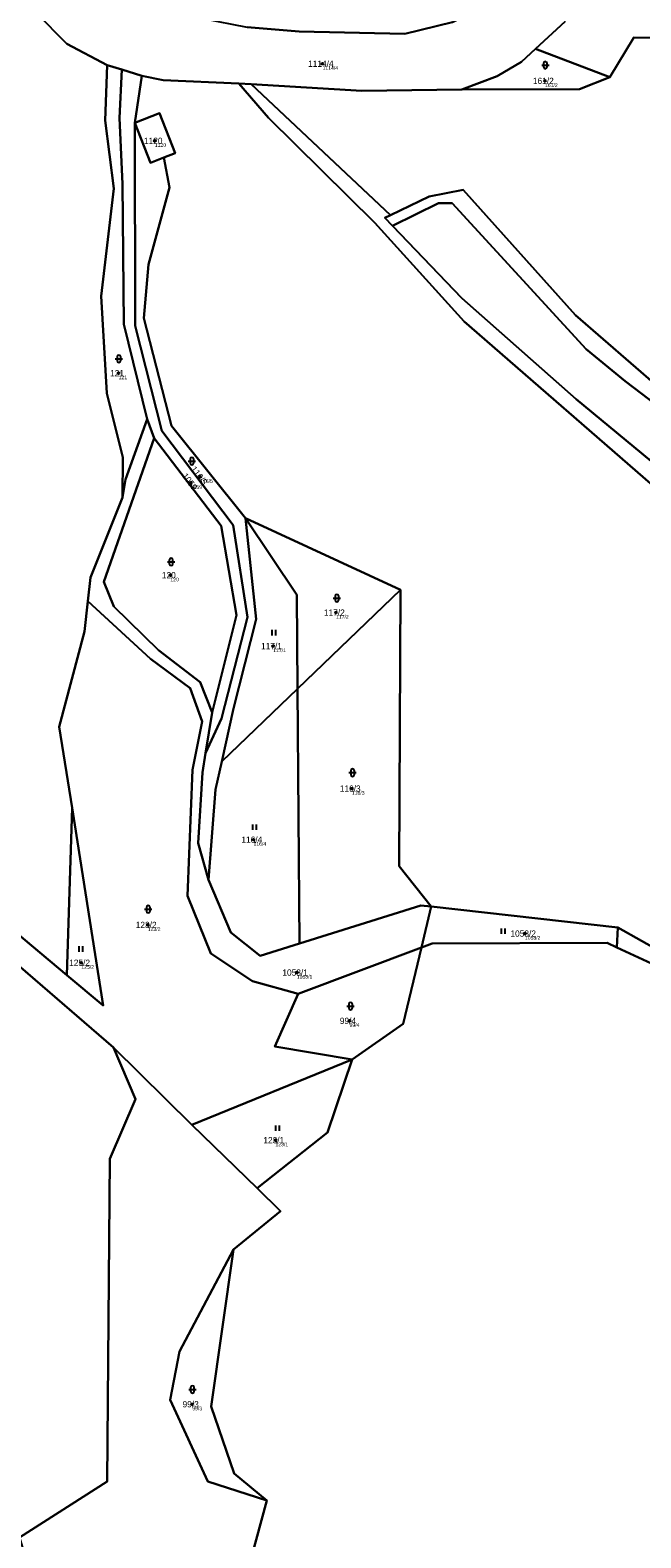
# Model space of a CAD drawing. Extents: x -554500 to -548272, y -1079733 to -1073730.
# Drawn here: x -552811.3 to -552644.9, y -1077438.3 to -1077027.7 of the extents above; entities that cross this region are included whole.
import ezdxf

# ---------------------------------------------------------------- set-up
doc = ezdxf.new("R2010")
doc.units = 0
for name, color, linetype in [('Definiční body', 7, 'Continuous'), ('Hranice parcel', 7, 'Continuous'), ('Parcelní čísla', 7, 'Continuous'), ('Polygon parcely', 7, 'Continuous'), ('Značky kultur', 7, 'Continuous')]:
    doc.layers.add(name, color=color, linetype=linetype)

msp = doc.modelspace()

# ---------------------------------------------------------------- linework, layer by layer
at = {"layer": 'Definiční body'}
for centre in [(-552731.61, -1077036.85994), (-552671.02, -1077041.52994), (-552777.3, -1077057.84994), (-552787.17, -1077121.10994), (-552767.53, -1077150.99994), (-552764.95, -1077149.35994), (-552773.07, -1077176.13994), (-552727.95, -1077186.31994), (-552745.07, -1077195.43994), (-552723.63, -1077234.24994), (-552750.43, -1077248.15994), (-552779.22, -1077271.36994), (-552676.49, -1077273.72994), (-552797.34, -1077281.66994), (-552738.62, -1077284.33994), (-552724.27, -1077297.48994), (-552744.45, -1077329.98994), (-552767.11, -1077401.89994)]:
    msp.add_circle(centre, 0.25, dxfattribs=at)
at = {"layer": 'Hranice parcel'}
for p, q in [((-552665.53, -1077025.33), (-552673.59, -1077032.78)), ((-552673.59, -1077032.78), (-552653.4, -1077040.52)), ((-552786.28, -1077038.47), (-552790.28, -1077037.21)), ((-552780.86, -1077040.17), (-552786.28, -1077038.47)), ((-552782.79, -1077052.97), (-552780.86, -1077040.17)), ((-552751.02, -1077042.45), (-552754.44, -1077042.24)), ((-552713.14, -1077078.13), (-552751.02, -1077042.45)), ((-552777.52, -1077138.83), (-552779.42, -1077133.62)), ((-552710.35, -1077180.11), (-552752.62, -1077160.65)), ((-552710.35, -1077180.11), (-552738.46, -1077207.05)), ((-552738.46, -1077207.05), (-552759.1, -1077226.83)), ((-552738.46, -1077207.05), (-552737.9, -1077276.43)), ((-552763.49, -1077224.58), (-552761.73, -1077213.52)), ((-552801.28, -1077285.01), (-552799.86, -1077239.46)), ((-552801.28, -1077285.01), (-552841.18, -1077251.64)), ((-552788.55, -1077304.75), (-552844.64, -1077256.35)), ((-552704.66, -1077277.49), (-552701.99, -1077266.38)), ((-552651.16, -1077272.05), (-552701.99, -1077266.38)), ((-552651.47, -1077277.5), (-552651.16, -1077272.05)), ((-552638.3, -1077279.34), (-552651.16, -1077272.05)), ((-552704.66, -1077277.49), (-552738.29, -1077290.17)), ((-552767.19, -1077325.78), (-552788.55, -1077304.75)), ((-552723.58, -1077307.99), (-552767.19, -1077325.78)), ((-552749.44, -1077343.09), (-552767.19, -1077325.78))]:
    msp.add_line(p, q, dxfattribs=at)
for points in [[(-552805.21, -1076999.91), (-552796.09, -1077011.92), (-552787.96, -1077017.54), (-552784.15, -1077019.17), (-552776.33, -1077022.15), (-552752.12, -1077026.89), (-552738.02, -1077028.06), (-552709.18, -1077028.68), (-552696.24, -1077025.5), (-552682.97, -1077018.58), (-552675.22, -1077011.97), (-552652.82, -1076990.23)], [(-552790.28, -1077037.21), (-552801.32, -1077031.45), (-552809.74, -1077022.87), (-552827.85, -1076998.45)], [(-552673.59, -1077032.78), (-552677.43, -1077036.32), (-552684.05, -1077040.25), (-552693.64, -1077043.85)], [(-552653.4, -1077040.52), (-552646.86, -1077029.76), (-552624.45, -1077030.16), (-552597.47, -1077040.98), (-552582.84, -1077051.52), (-552573.74, -1077062.51), (-552541.1, -1077125.95), (-552535.28, -1077141.98), (-552500.58, -1077183.57), (-552484.84, -1077224.94), (-552483.73, -1077240.24), (-552477.24, -1077252.97), (-552476.8, -1077265.1)], [(-552790.28, -1077037.21), (-552790.84, -1077052.29), (-552788.5, -1077070.86), (-552791.92, -1077100.14), (-552790.34, -1077126.56), (-552786, -1077144.13), (-552786.09, -1077154.96)], [(-552779.42, -1077133.62), (-552785.78, -1077107.8), (-552786.1, -1077069.57), (-552786.9, -1077051.73), (-552786.28, -1077038.47)], [(-552780.86, -1077040.17), (-552775.06, -1077041.37), (-552754.44, -1077042.24)], [(-552653.4, -1077040.52), (-552661.58, -1077043.75), (-552693.64, -1077043.85)], [(-552754.44, -1077042.24), (-552746.3, -1077051.58), (-552717.37, -1077080.17), (-552693.04, -1077107.1), (-552638.13, -1077154.8), (-552603.73, -1077178.22), (-552577.89, -1077200.85), (-552553.67, -1077225.19), (-552518.05, -1077258.47), (-552487.02, -1077289.2)], [(-552693.64, -1077043.85), (-552720.94, -1077044.25), (-552751.02, -1077042.45)], [(-552774.83, -1077062.44), (-552771.73, -1077061.22), (-552776.05, -1077050.3), (-552782.79, -1077052.97)], [(-552774.83, -1077062.44), (-552778.47, -1077063.89), (-552782.79, -1077052.97)], [(-552782.79, -1077052.97), (-552782.69, -1077108.27), (-552775.41, -1077136.87), (-552755.95, -1077162.5), (-552752.08, -1077187.6), (-552759.18, -1077215.17), (-552763.49, -1077224.58)], [(-552752.62, -1077160.65), (-552772.79, -1077135.47), (-552780.31, -1077106.19), (-552779.01, -1077091.53), (-552773.27, -1077070.61), (-552774.83, -1077062.44)], [(-552476.8, -1077265.1), (-552489.86, -1077252.25), (-552539.07, -1077208.1), (-552586.76, -1077160.47), (-552599.88, -1077151.51), (-552619.68, -1077140.24), (-552640.06, -1077124.94), (-552662.67, -1077105.32), (-552693.33, -1077071.21), (-552702.61, -1077073.03), (-552713.14, -1077078.13)], [(-552478.63, -1077269.41), (-552542.48, -1077211.84), (-552572.59, -1077182.17), (-552592.21, -1077162.02), (-552627.59, -1077139.76), (-552649.14, -1077123.28), (-552659.79, -1077114.63), (-552696.32, -1077074.8), (-552700.01, -1077074.81), (-552712.57, -1077081.01)], [(-552712.57, -1077081.01), (-552714.62, -1077078.84), (-552713.14, -1077078.13)], [(-552712.57, -1077081.01), (-552693.7, -1077100.73), (-552662.54, -1077128.22), (-552640.05, -1077146.78), (-552599.65, -1077176.96), (-552576.15, -1077197.49), (-552551, -1077222.01), (-552528.61, -1077242.66), (-552484.99, -1077284.42)], [(-552786.09, -1077154.96), (-552785.27, -1077150.08), (-552779.42, -1077133.62)], [(-552777.52, -1077138.83), (-552791.17, -1077177.91), (-552788.44, -1077184.63), (-552776.28, -1077196.53), (-552764.96, -1077205.25), (-552761.73, -1077213.52)], [(-552761.73, -1077213.52), (-552755.08, -1077186.99), (-552759.26, -1077162.72), (-552777.52, -1077138.83)], [(-552795.55, -1077183.21), (-552794.82, -1077176.81), (-552786.09, -1077154.96)], [(-552759.1, -1077226.83), (-552755.89, -1077212.41), (-552749.69, -1077188.09), (-552752.62, -1077160.65)], [(-552738.46, -1077207.05), (-552738.66, -1077181.5), (-552752.62, -1077160.65)], [(-552701.99, -1077266.38), (-552710.72, -1077255.41), (-552710.35, -1077180.11)], [(-552795.55, -1077183.21), (-552796.5, -1077191.49), (-552803.34, -1077217.43), (-552799.86, -1077239.46)], [(-552738.29, -1077290.17), (-552750.74, -1077286.66), (-552762.01, -1077279.12), (-552768.44, -1077263.43), (-552767.06, -1077229.18), (-552764.41, -1077216.02), (-552767.68, -1077206.93), (-552778.46, -1077198.92), (-552795.55, -1077183.21)], [(-552763.49, -1077224.58), (-552764.34, -1077229.9), (-552765.51, -1077249.1), (-552762.67, -1077259.09)], [(-552759.1, -1077226.83), (-552760.81, -1077234.48), (-552762.67, -1077259.09)], [(-552799.86, -1077239.46), (-552791.36, -1077293.31), (-552801.28, -1077285.01)], [(-552762.67, -1077259.09), (-552756.57, -1077273.48), (-552748.64, -1077279.8), (-552737.9, -1077276.43)], [(-552737.9, -1077276.43), (-552704.88, -1077266.06), (-552701.99, -1077266.38)], [(-552704.66, -1077277.49), (-552709.68, -1077298.34), (-552723.58, -1077307.99)], [(-552651.47, -1077277.5), (-552654.1, -1077276.28), (-552701.8, -1077276.41), (-552704.66, -1077277.49)], [(-552576.25, -1077376.33), (-552603.81, -1077361.54), (-552633.04, -1077349.32), (-552636.22, -1077339.19), (-552628.43, -1077303.5), (-552639.68, -1077282.97), (-552651.47, -1077277.5)], [(-552738.29, -1077290.17), (-552744.61, -1077304.51), (-552723.58, -1077307.99)], [(-552814.18, -1077438.2), (-552790.32, -1077422.91), (-552789.58, -1077335.11), (-552782.56, -1077318.81), (-552788.55, -1077304.75)], [(-552723.58, -1077307.99), (-552730.31, -1077327.86), (-552749.44, -1077343.09)], [(-552755.92, -1077359.75), (-552743.05, -1077349.32), (-552749.44, -1077343.09)], [(-552746.76, -1077428.1), (-552762.91, -1077422.95), (-552773.13, -1077400.7), (-552770.63, -1077387.54), (-552755.92, -1077359.75)], [(-552755.92, -1077359.75), (-552761.99, -1077402.52), (-552755.65, -1077420.71), (-552746.76, -1077428.1)], [(-552718.43, -1077507.71), (-552730.56, -1077479.12), (-552740.95, -1077471.44), (-552752.64, -1077449.51), (-552746.76, -1077428.1)]]:
    msp.add_lwpolyline(points, dxfattribs=at)
at = {"layer": 'Polygon parcely'}
for points in [[(-552776.33, -1077022.15), (-552752.12, -1077026.89), (-552738.02, -1077028.06), (-552709.18, -1077028.68), (-552696.24, -1077025.5), (-552682.97, -1077018.58), (-552675.22, -1077011.97), (-552652.82, -1076990.23), (-552665.24, -1076993.3), (-552745.16, -1077003.8), (-552805.21, -1076999.91), (-552796.09, -1077011.92), (-552787.96, -1077017.54), (-552784.15, -1077019.17)], [(-552684.05, -1077040.25), (-552693.64, -1077043.85), (-552661.58, -1077043.75), (-552653.4, -1077040.52), (-552673.59, -1077032.78), (-552677.43, -1077036.32)], [(-552786, -1077144.13), (-552786.09, -1077154.96), (-552785.27, -1077150.08), (-552779.42, -1077133.62), (-552785.78, -1077107.8), (-552786.1, -1077069.57), (-552786.9, -1077051.73), (-552786.28, -1077038.47), (-552790.28, -1077037.21), (-552790.84, -1077052.29), (-552788.5, -1077070.86), (-552791.92, -1077100.14), (-552790.34, -1077126.56)], [(-552780.86, -1077040.17), (-552786.28, -1077038.47), (-552786.9, -1077051.73), (-552786.1, -1077069.57), (-552785.78, -1077107.8), (-552779.42, -1077133.62), (-552777.52, -1077138.83), (-552759.26, -1077162.72), (-552755.08, -1077186.99), (-552761.73, -1077213.52), (-552763.49, -1077224.58), (-552759.18, -1077215.17), (-552752.08, -1077187.6), (-552755.95, -1077162.5), (-552775.41, -1077136.87), (-552782.69, -1077108.27), (-552782.79, -1077052.97)], [(-552751.02, -1077042.45), (-552754.44, -1077042.24), (-552746.3, -1077051.58), (-552717.37, -1077080.17), (-552693.04, -1077107.1), (-552638.13, -1077154.8), (-552603.73, -1077178.22), (-552577.89, -1077200.85), (-552553.67, -1077225.19), (-552518.05, -1077258.47), (-552487.02, -1077289.2), (-552484.99, -1077284.42), (-552528.61, -1077242.66), (-552551, -1077222.01), (-552576.15, -1077197.49), (-552599.65, -1077176.96), (-552640.05, -1077146.78), (-552662.54, -1077128.22), (-552693.7, -1077100.73), (-552712.57, -1077081.01), (-552714.62, -1077078.84), (-552713.14, -1077078.13)], [(-552771.73, -1077061.22), (-552776.05, -1077050.3), (-552782.79, -1077052.97), (-552778.47, -1077063.89), (-552774.83, -1077062.44)], [(-552775.41, -1077136.87), (-552755.95, -1077162.5), (-552752.08, -1077187.6), (-552759.18, -1077215.17), (-552763.49, -1077224.58), (-552764.34, -1077229.9), (-552765.51, -1077249.1), (-552762.67, -1077259.09), (-552760.81, -1077234.48), (-552759.1, -1077226.83), (-552755.89, -1077212.41), (-552749.69, -1077188.09), (-552752.62, -1077160.65), (-552772.79, -1077135.47), (-552780.31, -1077106.19), (-552779.01, -1077091.53), (-552773.27, -1077070.61), (-552774.83, -1077062.44), (-552778.47, -1077063.89), (-552782.79, -1077052.97), (-552782.69, -1077108.27)], [(-552599.88, -1077151.51), (-552619.68, -1077140.24), (-552640.06, -1077124.94), (-552662.67, -1077105.32), (-552693.33, -1077071.21), (-552702.61, -1077073.03), (-552713.14, -1077078.13), (-552714.62, -1077078.84), (-552712.57, -1077081.01), (-552700.01, -1077074.81), (-552696.32, -1077074.8), (-552659.79, -1077114.63), (-552649.14, -1077123.28), (-552627.59, -1077139.76), (-552592.21, -1077162.02), (-552572.59, -1077182.17), (-552542.48, -1077211.84), (-552478.63, -1077269.41), (-552476.8, -1077265.1), (-552489.86, -1077252.25), (-552539.07, -1077208.1), (-552586.76, -1077160.47)], [(-552528.61, -1077242.66), (-552484.99, -1077284.42), (-552478.63, -1077269.41), (-552542.48, -1077211.84), (-552572.59, -1077182.17), (-552592.21, -1077162.02), (-552627.59, -1077139.76), (-552649.14, -1077123.28), (-552659.79, -1077114.63), (-552696.32, -1077074.8), (-552700.01, -1077074.81), (-552712.57, -1077081.01), (-552693.7, -1077100.73), (-552662.54, -1077128.22), (-552640.05, -1077146.78), (-552599.65, -1077176.96), (-552576.15, -1077197.49), (-552551, -1077222.01)], [(-552777.52, -1077138.83), (-552779.42, -1077133.62), (-552785.27, -1077150.08), (-552786.09, -1077154.96), (-552794.82, -1077176.81), (-552795.55, -1077183.21), (-552778.46, -1077198.92), (-552767.68, -1077206.93), (-552764.41, -1077216.02), (-552767.06, -1077229.18), (-552768.44, -1077263.43), (-552762.01, -1077279.12), (-552750.74, -1077286.66), (-552738.29, -1077290.17), (-552704.66, -1077277.49), (-552701.99, -1077266.38), (-552704.88, -1077266.06), (-552737.9, -1077276.43), (-552748.64, -1077279.8), (-552756.57, -1077273.48), (-552762.67, -1077259.09), (-552765.51, -1077249.1), (-552764.34, -1077229.9), (-552763.49, -1077224.58), (-552761.73, -1077213.52), (-552764.96, -1077205.25), (-552776.28, -1077196.53), (-552788.44, -1077184.63), (-552791.17, -1077177.91)], [(-552759.26, -1077162.72), (-552777.52, -1077138.83), (-552791.17, -1077177.91), (-552788.44, -1077184.63), (-552776.28, -1077196.53), (-552764.96, -1077205.25), (-552761.73, -1077213.52), (-552755.08, -1077186.99)], [(-552738.66, -1077181.5), (-552752.62, -1077160.65), (-552749.69, -1077188.09), (-552755.89, -1077212.41), (-552759.1, -1077226.83), (-552738.46, -1077207.05)], [(-552752.62, -1077160.65), (-552738.66, -1077181.5), (-552738.46, -1077207.05), (-552710.35, -1077180.11)], [(-552710.72, -1077255.41), (-552710.35, -1077180.11), (-552738.46, -1077207.05), (-552737.9, -1077276.43), (-552704.88, -1077266.06), (-552701.99, -1077266.38)], [(-552796.5, -1077191.49), (-552803.34, -1077217.43), (-552799.86, -1077239.46), (-552791.36, -1077293.31), (-552801.28, -1077285.01), (-552841.18, -1077251.64), (-552844.64, -1077256.35), (-552788.55, -1077304.75), (-552767.19, -1077325.78), (-552723.58, -1077307.99), (-552744.61, -1077304.51), (-552738.29, -1077290.17), (-552750.74, -1077286.66), (-552762.01, -1077279.12), (-552768.44, -1077263.43), (-552767.06, -1077229.18), (-552764.41, -1077216.02), (-552767.68, -1077206.93), (-552778.46, -1077198.92), (-552795.55, -1077183.21)], [(-552748.64, -1077279.8), (-552737.9, -1077276.43), (-552738.46, -1077207.05), (-552759.1, -1077226.83), (-552760.81, -1077234.48), (-552762.67, -1077259.09), (-552756.57, -1077273.48)], [(-552801.28, -1077285.01), (-552791.36, -1077293.31), (-552799.86, -1077239.46)], [(-552651.16, -1077272.05), (-552701.99, -1077266.38), (-552704.66, -1077277.49), (-552701.8, -1077276.41), (-552654.1, -1077276.28), (-552651.47, -1077277.5)], [(-552704.66, -1077277.49), (-552738.29, -1077290.17), (-552744.61, -1077304.51), (-552723.58, -1077307.99), (-552709.68, -1077298.34)], [(-552814.18, -1077438.2), (-552812.92, -1077442.41), (-552802.21, -1077490.63), (-552792.48, -1077506.22), (-552767.39, -1077531.22), (-552747.77, -1077536.2), (-552740.65, -1077529.91), (-552718.43, -1077507.71), (-552730.56, -1077479.12), (-552740.95, -1077471.44), (-552752.64, -1077449.51), (-552746.76, -1077428.1), (-552762.91, -1077422.95), (-552773.13, -1077400.7), (-552770.63, -1077387.54), (-552755.92, -1077359.75), (-552743.05, -1077349.32), (-552749.44, -1077343.09), (-552767.19, -1077325.78), (-552788.55, -1077304.75), (-552782.56, -1077318.81), (-552789.58, -1077335.11), (-552790.32, -1077422.91)], [(-552767.19, -1077325.78), (-552749.44, -1077343.09), (-552730.31, -1077327.86), (-552723.58, -1077307.99)], [(-552755.92, -1077359.75), (-552770.63, -1077387.54), (-552773.13, -1077400.7), (-552762.91, -1077422.95), (-552746.76, -1077428.1), (-552755.65, -1077420.71), (-552761.99, -1077402.52)]]:
    msp.add_lwpolyline(points, close=True, dxfattribs=at)
for points in [[(-553044.61, -1077004.06), (-552978.82, -1077104.33), (-552881.84, -1077206.3), (-552841.18, -1077251.64), (-552801.28, -1077285.01), (-552799.86, -1077239.46), (-552803.34, -1077217.43), (-552796.5, -1077191.49), (-552795.55, -1077183.21), (-552794.82, -1077176.81), (-552786.09, -1077154.96), (-552786, -1077144.13), (-552790.34, -1077126.56), (-552791.92, -1077100.14), (-552788.5, -1077070.86), (-552790.84, -1077052.29), (-552790.28, -1077037.21), (-552801.32, -1077031.45), (-552809.74, -1077022.87)], [(-553088.19, -1077027.01), (-552985.99, -1077147.62), (-552933.72, -1077198.89), (-552901.01, -1077235.78), (-552861.41, -1077268.32), (-552864.7, -1077296.68), (-552876.19, -1077304.96), (-552869.04, -1077332.78), (-552857.32, -1077356.74), (-552823.97, -1077405.02), (-552814.18, -1077438.2), (-552790.32, -1077422.91), (-552789.58, -1077335.11), (-552782.56, -1077318.81), (-552788.55, -1077304.75), (-552844.64, -1077256.35), (-552874.93, -1077221.44), (-552913.63, -1077181.25), (-552981.06, -1077107.64), (-553022.78, -1077046.48), (-553047.15, -1077007.87)], [(-552809.74, -1077022.87), (-552801.32, -1077031.45), (-552790.28, -1077037.21), (-552786.28, -1077038.47), (-552780.86, -1077040.17), (-552775.06, -1077041.37), (-552754.44, -1077042.24), (-552751.02, -1077042.45), (-552720.94, -1077044.25), (-552693.64, -1077043.85), (-552684.05, -1077040.25), (-552677.43, -1077036.32), (-552673.59, -1077032.78), (-552665.53, -1077025.33)], [(-552696.24, -1077025.5), (-552709.18, -1077028.68), (-552738.02, -1077028.06), (-552752.12, -1077026.89)], [(-552665.53, -1077025.33), (-552673.59, -1077032.78), (-552653.4, -1077040.52), (-552646.86, -1077029.76), (-552624.45, -1077030.16)], [(-552624.45, -1077030.16), (-552646.86, -1077029.76), (-552653.4, -1077040.52), (-552661.58, -1077043.75), (-552693.64, -1077043.85), (-552720.94, -1077044.25), (-552751.02, -1077042.45), (-552713.14, -1077078.13), (-552702.61, -1077073.03), (-552693.33, -1077071.21), (-552662.67, -1077105.32), (-552640.06, -1077124.94)], [(-552638.13, -1077154.8), (-552693.04, -1077107.1), (-552717.37, -1077080.17), (-552746.3, -1077051.58), (-552754.44, -1077042.24), (-552775.06, -1077041.37), (-552780.86, -1077040.17), (-552782.79, -1077052.97), (-552776.05, -1077050.3), (-552771.73, -1077061.22), (-552774.83, -1077062.44), (-552773.27, -1077070.61), (-552779.01, -1077091.53), (-552780.31, -1077106.19), (-552772.79, -1077135.47), (-552752.62, -1077160.65), (-552710.35, -1077180.11), (-552710.72, -1077255.41), (-552701.99, -1077266.38), (-552651.16, -1077272.05), (-552638.3, -1077279.34)], [(-552473.23, -1077492.5), (-552525.21, -1077414.79), (-552561.07, -1077381.56), (-552603.6, -1077358.49), (-552630.95, -1077347.33), (-552633.72, -1077337.84), (-552625.91, -1077301.85), (-552638.3, -1077279.34), (-552651.16, -1077272.05), (-552651.47, -1077277.5), (-552639.68, -1077282.97), (-552628.43, -1077303.5), (-552636.22, -1077339.19), (-552633.04, -1077349.32), (-552603.81, -1077361.54), (-552576.25, -1077376.33), (-552563.13, -1077383.33), (-552528.11, -1077416.15), (-552476.28, -1077492.8)], [(-552492.14, -1077480), (-552531.25, -1077419.85), (-552576.25, -1077376.33), (-552603.81, -1077361.54), (-552633.04, -1077349.32), (-552636.22, -1077339.19), (-552628.43, -1077303.5), (-552639.68, -1077282.97), (-552651.47, -1077277.5), (-552654.1, -1077276.28), (-552701.8, -1077276.41), (-552704.66, -1077277.49), (-552709.68, -1077298.34), (-552723.58, -1077307.99), (-552730.31, -1077327.86), (-552749.44, -1077343.09), (-552743.05, -1077349.32), (-552755.92, -1077359.75), (-552761.99, -1077402.52), (-552755.65, -1077420.71), (-552746.76, -1077428.1), (-552752.64, -1077449.51)]]:
    msp.add_lwpolyline(points, dxfattribs=at)
at = {"layer": 'Značky kultur'}
for p, q in [((-552671.421, -1077036.751), (-552671.421, -1077037.752)), ((-552670.419, -1077037.752), (-552670.419, -1077036.751)), ((-552671.921, -1077037.251), (-552669.919, -1077037.251)), ((-552788.091, -1077117.181), (-552786.089, -1077117.181)), ((-552787.591, -1077116.681), (-552787.591, -1077117.682)), ((-552786.589, -1077117.682), (-552786.589, -1077116.681)), ((-552768.201, -1077145.071), (-552766.199, -1077145.071)), ((-552767.701, -1077144.571), (-552767.701, -1077145.572)), ((-552766.699, -1077145.572), (-552766.699, -1077144.571)), ((-552773.871, -1077172.511), (-552771.869, -1077172.511)), ((-552773.371, -1077172.011), (-552773.371, -1077173.012)), ((-552772.369, -1077173.012), (-552772.369, -1077172.011)), ((-552728.701, -1077182.351), (-552726.699, -1077182.351)), ((-552728.201, -1077181.851), (-552728.201, -1077182.852)), ((-552727.199, -1077182.852), (-552727.199, -1077181.851)), ((-552745.361, -1077192.55), (-552745.361, -1077191.05)), ((-552744.36, -1077192.55), (-552744.36, -1077191.05)), ((-552724.431, -1077229.911), (-552722.429, -1077229.911)), ((-552723.931, -1077229.411), (-552723.931, -1077230.412)), ((-552722.929, -1077230.412), (-552722.929, -1077229.411)), ((-552750.641, -1077245.51), (-552750.641, -1077244.01)), ((-552749.64, -1077245.51), (-552749.64, -1077244.01)), ((-552779.591, -1077266.591), (-552779.591, -1077267.592)), ((-552778.589, -1077267.592), (-552778.589, -1077266.591)), ((-552780.091, -1077267.091), (-552778.089, -1077267.091)), ((-552682.891, -1077273.84), (-552682.891, -1077272.34)), ((-552681.89, -1077273.84), (-552681.89, -1077272.34)), ((-552797.961, -1077278.67), (-552797.961, -1077277.17)), ((-552796.96, -1077278.67), (-552796.96, -1077277.17)), ((-552724.991, -1077293.481), (-552722.989, -1077293.481)), ((-552724.491, -1077292.981), (-552724.491, -1077293.982)), ((-552723.489, -1077293.982), (-552723.489, -1077292.981)), ((-552744.351, -1077327.45), (-552744.351, -1077325.95)), ((-552743.35, -1077327.45), (-552743.35, -1077325.95)), ((-552768.061, -1077397.841), (-552766.059, -1077397.841)), ((-552767.561, -1077397.341), (-552767.561, -1077398.342)), ((-552766.559, -1077398.342), (-552766.559, -1077397.341))]:
    msp.add_line(p, q, dxfattribs=at)
for centre, start, end in [((-552670.92, -1077036.7509), 0, 180), ((-552670.92, -1077037.7509), 180, 359.9878861), ((-552787.09, -1077116.6809), 0, 180), ((-552787.09, -1077117.6809), 180, 359.9878861), ((-552767.2, -1077144.5709), 0, 180), ((-552767.2, -1077145.5709), 180, 359.9878861), ((-552772.87, -1077172.0109), 0, 180), ((-552772.87, -1077173.0109), 180, 359.9878861), ((-552727.7, -1077181.8509), 0, 180), ((-552727.7, -1077182.8509), 180, 359.9878861), ((-552723.43, -1077229.4109), 0, 180), ((-552723.43, -1077230.4109), 180, 359.9878861), ((-552779.09, -1077266.5909), 0, 180), ((-552779.09, -1077267.5909), 180, 359.9878861), ((-552723.99, -1077292.9809), 0, 180), ((-552723.99, -1077293.9809), 180, 359.9878861), ((-552767.06, -1077397.3409), 0, 180), ((-552767.06, -1077398.3409), 180, 359.9878861)]:
    msp.add_arc(centre, 0.5, start, end, dxfattribs=at)

# ---------------------------------------------------------------- texts
at = {"layer": 'Definiční body'}
for s, p in [('1114/4', (-552731.61, -1077038.516)), ('161/2', (-552671.02, -1077043.186)), ('1120', (-552777.3, -1077059.506)), ('121', (-552787.17, -1077122.766)), ('1059', (-552767.53, -1077152.656)), ('116/5', (-552764.95, -1077151.016)), ('120', (-552773.07, -1077177.796)), ('117/2', (-552727.95, -1077187.976)), ('117/1', (-552745.07, -1077197.096)), ('116/3', (-552723.63, -1077235.906)), ('116/4', (-552750.43, -1077249.816)), ('123/2', (-552779.22, -1077273.026)), ('1058/2', (-552676.49, -1077275.386)), ('125/2', (-552797.34, -1077283.326)), ('1058/1', (-552738.62, -1077285.996)), ('99/4', (-552724.27, -1077299.146)), ('123/1', (-552744.45, -1077331.646)), ('99/3', (-552767.11, -1077403.556))]:
    msp.add_text(s, height=0.999996, dxfattribs=at).set_placement(p)
at = {"layer": 'Parcelní čísla'}
for s, p in [('1114/4', (-552735.557, -1077037.71)), ('161/2', (-552674.318, -1077042.38)), ('1120', (-552780.274, -1077058.7)), ('121', (-552789.495, -1077121.96)), ('120', (-552775.395, -1077176.99)), ('117/2', (-552731.248, -1077187.17)), ('117/1', (-552748.368, -1077196.29)), ('116/3', (-552726.928, -1077235.1)), ('116/4', (-552753.728, -1077249.01)), ('123/2', (-552782.518, -1077272.22)), ('1058/2', (-552680.437, -1077274.58)), ('125/2', (-552800.638, -1077282.52)), ('1058/1', (-552742.567, -1077285.19)), ('99/4', (-552726.919, -1077298.34)), ('123/1', (-552747.748, -1077330.84)), ('99/3', (-552769.759, -1077402.75))]:
    msp.add_text(s, height=1.699998, dxfattribs=at).set_placement(p)
for s, p in [('116/5', (-552767.613, -1077147.237)), ('1059', (-552769.998, -1077149.136))]:
    msp.add_text(s, height=1.699998, rotation=307, dxfattribs=at).set_placement(p)

doc.saveas('drawing.dxf')
